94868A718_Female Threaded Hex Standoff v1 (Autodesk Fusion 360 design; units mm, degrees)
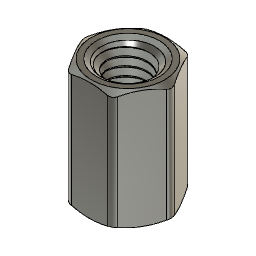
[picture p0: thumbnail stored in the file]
description: STEP AP203
part number: 94868A718_Female Threaded Hex Standoff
